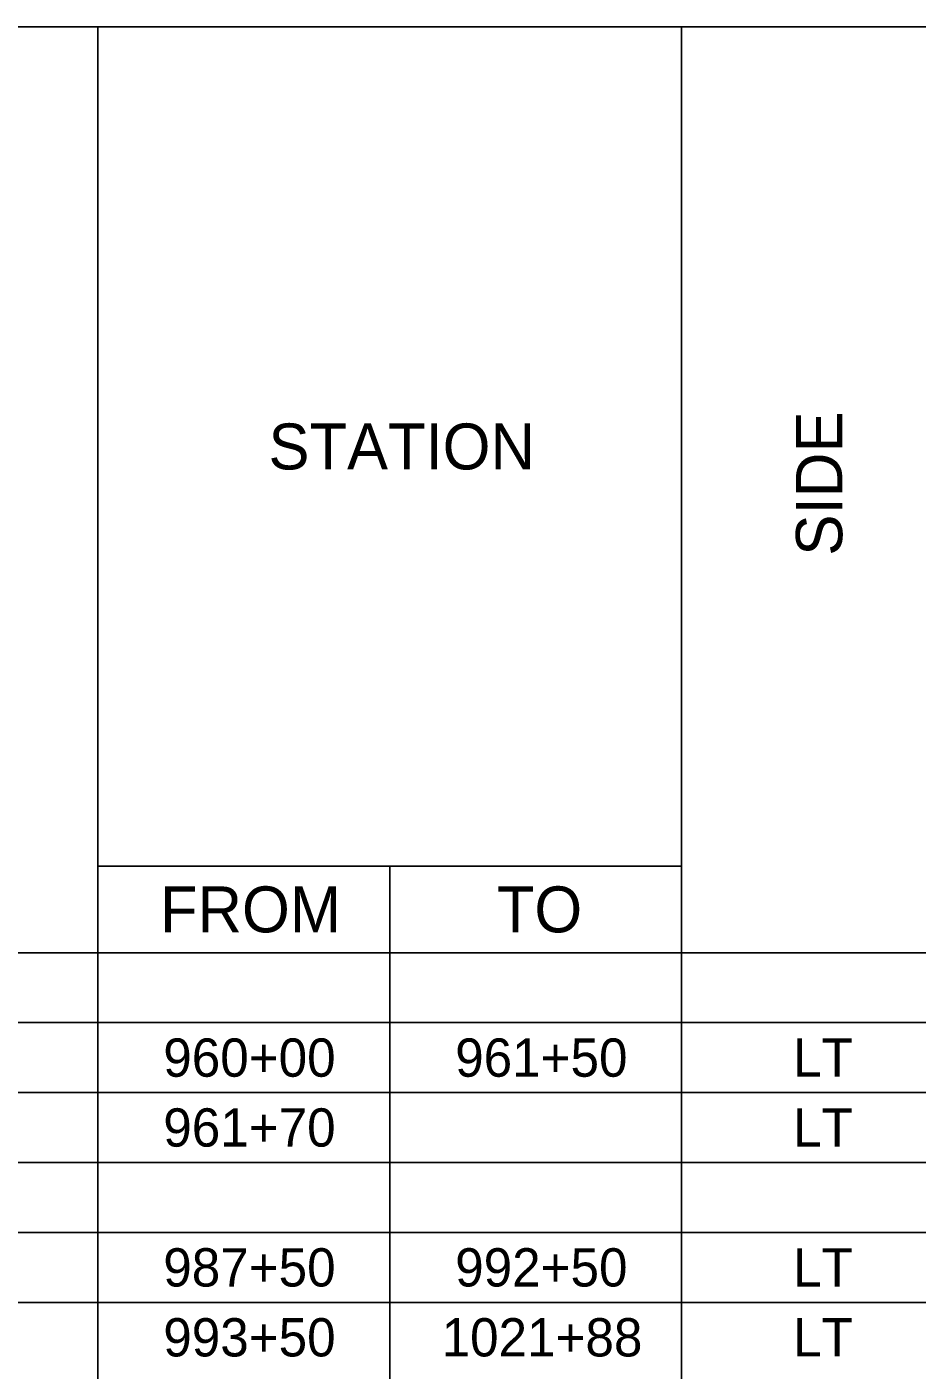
# Model space of a CAD drawing. Extents: x 91011267 to 91022583, y 37007614 to 37014266.
# Drawn here: x 91011467.7 to 91011642.6, y 37010961.6 to 37011225.5 of the extents above; entities that cross this region are included whole.
import ezdxf

# ---------------------------------------------------------------- set-up
doc = ezdxf.new("R2010")
doc.units = 0
doc.layers.add('SC_Scratch2', color=7, linetype='Continuous')
doc.layers.add('SH_Data', color=7, linetype='Continuous')

msp = doc.modelspace()

# ---------------------------------------------------------------- linework, layer by layer
at = {"layer": 'SC_Scratch2'}
msp.add_lwpolyline([(91011277.35, 37011225.45), (91012802.35, 37011225.45), (91012802.35, 37010175.45), (91011277.35, 37010175.45)], close=True, dxfattribs=at)
at = {"layer": 'SH_Data'}
for p, q in [((91011277.35, 37011225.45), (91011596.32, 37011225.45)), ((91011481.65, 37011225.45), (91011481.65, 37011134.52)), ((91011596.32, 37011225.45), (91011650.36, 37011225.45)), ((91011596.32, 37011225.45), (91011596.32, 37011134.52)), ((91011481.65, 37011134.52), (91011481.65, 37011060.59)), ((91011596.32, 37011134.52), (91011596.32, 37011060.59)), ((91011481.65, 37011060.59), (91011596.32, 37011060.59)), ((91011481.65, 37011060.59), (91011481.65, 37011043.58)), ((91011538.99, 37011060.59), (91011538.99, 37011043.58)), ((91011596.32, 37011060.59), (91011596.32, 37011043.58)), ((91011277.35, 37011043.58), (91011596.32, 37011043.58)), ((91011481.65, 37011043.58), (91011481.65, 37010933.68)), ((91011538.99, 37011043.58), (91011538.99, 37010933.68)), ((91011596.32, 37011043.58), (91011650.36, 37011043.58)), ((91011596.32, 37011043.58), (91011596.32, 37010933.68)), ((91011277.35, 37011029.85), (91011596.32, 37011029.85)), ((91011596.32, 37011029.85), (91011650.36, 37011029.85)), ((91011277.35, 37011016.11), (91011596.32, 37011016.11)), ((91011596.32, 37011016.11), (91011650.36, 37011016.11)), ((91011277.35, 37011002.37), (91011596.32, 37011002.37)), ((91011596.32, 37011002.37), (91011650.36, 37011002.37)), ((91011277.35, 37010988.63), (91011596.32, 37010988.63)), ((91011596.32, 37010988.63), (91011650.36, 37010988.63)), ((91011277.35, 37010974.89), (91011596.32, 37010974.89)), ((91011596.32, 37010974.89), (91011650.36, 37010974.89))]:
    msp.add_line(p, q, dxfattribs=at)

# ---------------------------------------------------------------- texts
msp.add_text('SIDE', height=9.095, rotation=90, dxfattribs=at).set_placement((91011627.89, 37011121.55))
for s, height, p in [('STATION', 9.028, (91011515.19, 37011138.51)), ('FROM', 9.028, (91011493.89, 37011047.57)), ('TO', 9.028, (91011560.04, 37011047.57)), ('960+00', 7.523, (91011494.52, 37011019.21)), ('961+50', 7.523, (91011551.86, 37011019.21)), ('LT', 7.523, (91011618.23, 37011019.21)), ('961+70', 7.523, (91011494.52, 37011005.48)), ('LT', 7.523, (91011618.23, 37011005.48)), ('987+50', 7.523, (91011494.52, 37010978)), ('992+50', 7.523, (91011551.86, 37010978)), ('LT', 7.523, (91011618.23, 37010978)), ('993+50', 7.523, (91011494.52, 37010964.26)), ('1021+88', 7.523, (91011549.19, 37010964.26)), ('LT', 7.523, (91011618.23, 37010964.26))]:
    msp.add_text(s, height=height, dxfattribs=at).set_placement(p)

doc.saveas('drawing.dxf')
